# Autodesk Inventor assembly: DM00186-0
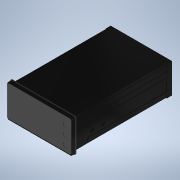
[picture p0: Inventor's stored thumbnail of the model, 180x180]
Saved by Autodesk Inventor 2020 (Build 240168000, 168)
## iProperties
Created: 2021-02
Part Number: DM00186-0
Document SubType Name: Assembly
Designer: zambolin
Title: C:\Users\Zambolin\Desktop\S301.stp
Author: zambolin
Sending System: Autodesk Inventor 2020
Preprocessor: ST-DEVELOPER v18
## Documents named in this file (27)
- C:\Users\Zambolin\Desktop\S301\DM00186-0.iam
- C:\Users\Zambolin\Desktop\S301\Sx1001.ipt
- C:\Users\Zambolin\Desktop\S301\Sx1002.ipt
- C:\Users\Zambolin\Desktop\S301\Sx1003.ipt
- C:\Users\Zambolin\Desktop\S301\Sx1004.ipt
- C:\Users\Zambolin\Desktop\S301\Sx1005.ipt
- C:\Users\Zambolin\Desktop\S301\Sx1006.ipt
- C:\Users\Zambolin\Desktop\S301\Sx1007.ipt
- C:\Users\Zambolin\Desktop\S301\Sx1008.ipt
- C:\Users\Zambolin\Desktop\S301\Sx1009.ipt
- C:\Users\Zambolin\Desktop\S301\Sx10010.ipt
- C:\Users\Zambolin\Desktop\S301\Sx10011.ipt
- C:\Users\Zambolin\Desktop\S301\Sx10012.ipt
- C:\Users\Zambolin\Desktop\S301\Sx10013.ipt
- C:\Users\Zambolin\Desktop\S301\Sx10014.ipt
- C:\Users\Zambolin\Desktop\S301\Sx10015.ipt
- C:\Users\Zambolin\Desktop\S301\Sx10016.ipt
- C:\Users\Zambolin\Desktop\S301\Sx10017.ipt
- C:\Users\Zambolin\Desktop\S301\Sx10018.ipt
- C:\Users\Zambolin\Desktop\S301\Sx10019.ipt
- C:\Users\Zambolin\Desktop\S301\Sx10020.ipt
- C:\Users\Zambolin\Desktop\S301\Sx10021.ipt
- C:\Users\Zambolin\Desktop\S301\Sx10022.ipt
- C:\Users\Zambolin\Desktop\S301\Sx10023.ipt
- C:\Users\Zambolin\Desktop\S301\Sx10024.ipt
- C:\Users\Zambolin\Desktop\S301\Sx10025.ipt
- C:\Users\Zambolin\Desktop\S301\Sx10026.ipt
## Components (26 placed, 26 different names)
1. Sx1001:1
2. Sx1002:1
3. Sx1003:1
4. Sx1004:1
5. Sx1005:1
6. Sx1006:1
7. Sx1007:1
8. Sx1008:1
9. Sx1009:1
10. Sx10010:1
11. Sx10011:1
12. Sx10012:1
13. Sx10013:1
14. Sx10014:1
15. Sx10015:1
16. Sx10016:1
17. Sx10017:1
18. Sx10018:1
19. Sx10019:1
20. Sx10020:1
21. Sx10021:1
22. Sx10022:1
23. Sx10023:1
24. Sx10024:1
25. Sx10025:1
26. Sx10026:1
